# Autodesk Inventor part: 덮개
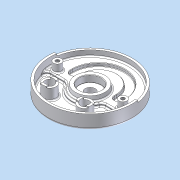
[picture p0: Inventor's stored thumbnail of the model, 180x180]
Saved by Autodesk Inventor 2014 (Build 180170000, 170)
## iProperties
Company: 한국ATC센터
Created: 2015-04
Part Number: 덮개
Document SubType Name: Modeling
Designer: KYOUNG IL JANG
Density: 2.71 g/cm^3
Material: 알루미늄-6061
Appearance: 매끄러움 - 흰색
Author: KYOUNG IL JANG
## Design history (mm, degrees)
sketch "스케치1"
  geometry: L1 (-59, -19)-(-59, 19); L2 (59, 19)-(59, -19); L3 (-41, 19)-(-41, -19); L4 (41, -19)-(41, 19); L5 (59, 5)-(41, 5); L6 (-41, 5)-(-59, 5); C1 r 90 at (0, 0); C2 r 95 at (0, 0); A1 r 59 centre (0, 19) between (59, 19) and (-59, 19); A2 r 59 centre (0, -19) between (-59, -19) and (59, -19); A3 r 41 centre (0, -19) between (-41, -19) and (41, -19); A4 r 41 centre (0, 19) between (41, 19) and (-41, 19); 2 further points
  constraints: 12 end point, 8 point on circle, 6 centre point, 4 point on line, 4 tangent, 2 parallel, 2 perpendicular, 1 coincident, 1 collinear, 1 horizontal alignment, 1 midpoint, 1 vertical, 1 vertical alignment, 3 other
  dimensions: "d2" = 180 diameter of C1; "d3" = 156 dimension on A2 A1; "d4" = 118 distance between parallel lines of L2 L1; "d5" = 18 distance between parallel lines of L2 L4; "d8" = 190 diameter of C2; "d121" = 5 distance from line of L5 point (0, 0)
extrude "돌출1" new body sketch "스케치1" distance "d6" = 14; taper "d7" = 0 deg
extrude "돌출2" join sketch "스케치1" distance "d9" = 13; taper "d10" = 0 deg
extrude "돌출3" cut sketch "스케치1" distance "d11" = 7; taper "d12" = 0 deg
sketch "스케치15"
  geometry: C1 r 26 at (0, 0); 1 further point
  constraints: 1 centre point, 1 coincident
  dimensions: "d123" = 52 diameter of C1
extrude "돌출13" join sketch "스케치15" distance "d124" = 12; taper "d125" = -7.5 deg
sketch "스케치2"
  geometry: C1 r 11.5 at (0, 0); 1 further point
  constraints: 1 centre point, 1 coincident
  dimensions: "d13" = 23 diameter of C1
extrude "돌출4" cut sketch "스케치2" stored distance "d14" = 7; taper "d15" = 0 deg
fillet "모깎기1"
fillet "모깎기2"
sketch "스케치3"
  geometry: L1 (-89.124, 12.526)-(-94.075, 13.221); L2 (89.124, 12.526)-(94.075, 13.221); L3 (0, 0)-(0, -90); A1 r 95 centre (0, 0) between (-94.075, 13.221) and (94.075, 13.221) reference; A2 r 90 centre (0, 0) between (-89.124, 12.526) and (89.124, 12.526) reference; 1 further point
  constraints: 6 end point, 5 point on circle, 1 point on line, 1 vertical, 1 other
  dimensions: "d16" = 196 deg dimension on L2 L1
extrude "돌출5" join sketch "스케치3" distance "d17" = 5; taper "d18" = 0 deg
hole "구멍1" diameter "d21" = 50; stored, may be unused: countersink angle "d25" = 90 deg, drill point angle "d27" = 0 deg; dims "d19" = 10, "d20" = 10, "d22" = 6, "d23" = 4, "d24" = 2, "d26" = 5
fillet "모깎기3" dims "d28" = 0.3
fillet "모깎기5" dims "d30" = 3
sketch "스케치4"
  geometry: C1 r 35 at (0, 0); C2 r 25 at (0, 0); 1 further point
  constraints: 2 centre point, 1 coincident
  dimensions: "d32" = 70 diameter of C1 (derived); "d36" = 10 radial gap between concentric circles of C1 C2
extrude "돌출6" join sketch "스케치4" distance "d33" = 10; taper "d34" = 0 deg
feature "면 기울기2" dims angle "d37" = 10 deg
chamfer "모따기1" distance "d39" = 1; stored, may be unused: second distance "d40" = 2, angle "d41" = 45 deg
fillet "모깎기7" dims "d42" = 5
sketch "스케치5"
  geometry: L1 (-38.833, -16)-(-88.566, -16); L2 (38.833, -16)-(88.566, -16); A1 r 90 centre (0, 0) between (-88.566, -16) and (88.566, -16) reference; A2 r 42 centre (0, 0) between (-38.833, -16) and (38.833, -16); 1 further point
  constraints: 4 end point, 4 point on circle, 1 centre point, 1 collinear, 1 horizontal, 1 point on line
  dimensions: "d43" = 48 radial gap between concentric circles of A1 A2; "d44" = 16 distance from line of point (0, 0) L1
extrude "돌출7" cut sketch "스케치5" stored distance "d45" = 10; taper "d46" = 0 deg
fillet "모깎기8" dims "d47" = 10
chamfer "모따기2" distance "d49" = 1; stored, may be unused: second distance "d50" = 2, angle "d51" = 45 deg
sketch "스케치8"
  geometry: C1 r 9 at (74, 0); C2 r 9 at (-74, 0); A1 r 74 centre (0, 0) between (74, 0) and (-74, 0); 1 further point
  constraints: 3 centre point, 2 horizontal alignment, 2 point on circle, 1 coincident, 1 equal radius
  dimensions: "d64" = 18 diameter of C1; "d65" = 148 diameter of A1
extrude "돌출9" join sketch "스케치8" stored distance "d66" = 5; taper "d67" = 0 deg
sketch "스케치11"
  geometry: C1 r 15 at (40, -52); C2 r 15 at (-40, -52); 1 further point
  constraints: 2 centre point, 1 equal radius, 1 horizontal alignment
  dimensions: "d82" = 52 vertical distance of point (0, 0) C1.centre; "d83" = 30 diameter of C1; "d84" = 80 distance of C2.centre C1.centre; "d85" = 40 horizontal distance of point (0, 0) C1.centre (= 0.5 x d84)
extrude "돌출10" join sketch "스케치11" stored distance "d86" = 10; taper "d87" = 0 deg
node "구멍3"
node "구멍5"
hole "구멍6" diameter "d92" = 20; stored, may be unused: countersink angle "d96" = 90 deg, drill point angle "d98" = 118 deg; dims "d90" = 10, "d91" = 10, "d93" = 6, "d94" = 4, "d95" = 2, "d97" = 8
hole "구멍7" diameter "d101" = 20; stored, may be unused: countersink angle "d105" = 90 deg, drill point angle "d107" = 118 deg; dims "d99" = 10, "d100" = 10, "d102" = 6, "d103" = 4, "d104" = 2, "d106" = 8
fillet "모깎기13" dims "d108" = 3
sketch "스케치13"
  geometry: L1 (-20.252, -58)-(-26, -58); L2 (-42, -58)-(-47.748, -58); L3 (-20.252, -46)-(-26, -46); L4 (-42, -46)-(-47.748, -46); L5 (-108, -65.748)-(-108, -60); L6 (-108, -44)-(-108, -38.252); L7 (-120, -44)-(-120, -38.252); L8 (-120, -60)-(-120, -65.748); A1 r 15 centre (-34, -52) between (-20.252, -58) and (-47.748, -58) reference; A2 r 10 centre (-34, -52) between (-26, -58) and (-42, -58) reference; A3 r 15 centre (-114, -52) between (-108, -65.748) and (-108, -38.252) reference; A4 r 10 centre (-114, -52) between (-108, -60) and (-108, -44) reference; 1 further point
  constraints: 16 end point, 16 point on circle, 3 equal length, 3 point on line, 2 collinear, 1 horizontal, 1 perpendicular
  dimensions: "d114" = 12 distance between parallel lines of L4 L2; "d115" = 6 distance from line of A1.centre L2 (= 0.5 x d114); "d116" = 12 distance between parallel lines of L8 L5 (= d114); "d117" = 6 distance from line of A3.centre L5 (= d115)
extrude "돌출12" join sketch "스케치13" distance "d118" = 3; taper "d119" = 0 deg
fillet "모깎기14" dims "d120" = 1
node "솔리드1"
sketch "스케치9"
  geometry: 1 further point
hole "구멍2" sketch "스케치9" diameter "d68" = 8.376; stored, may be unused: countersink angle "d72" = 90 deg, drill point angle "d74" = 120 deg; dims "d69" = 16, "d70" = 4, "d71" = 2, "d73" = 21
sketch "스케치10"
  geometry: 1 further point
hole "구멍4" sketch "스케치10" diameter "d75" = 8.376; stored, may be unused: countersink angle "d79" = 90 deg, drill point angle "d81" = 120 deg; dims "d76" = 16, "d77" = 4, "d78" = 2, "d80" = 21
